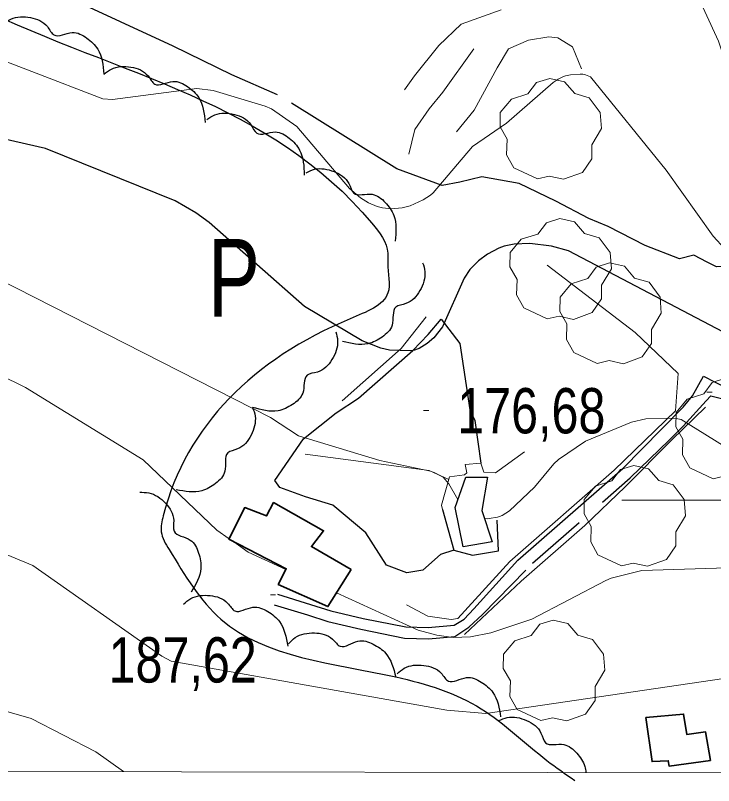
# Model space of a CAD drawing. Extents: x 483840 to 488445, y 4386047 to 4389027.
# Drawn here: x 484357.8 to 484492.8, y 4386444.9 to 4386593.6 of the extents above; entities that cross this region are included whole.
import ezdxf
from ezdxf.enums import TextEntityAlignment as Align

# ---------------------------------------------------------------- set-up
doc = ezdxf.new("R2010")
doc.units = 0
doc.header["$LTSCALE"] = 4
doc.linetypes.add('LONG_DASHED', pattern=[7.5, 6, -1.5])
doc.linetypes.add('MEDIUM_DASHED', pattern=[4.5, 3, -1.5])
for name, color, linetype, lineweight in [('1', 7, 'Continuous', 13), ('21', 7, 'Continuous', 25), ('25', 7, 'LONG_DASHED', 25), ('27', 7, 'Continuous', 25), ('29', 7, 'Continuous', 13), ('38', 7, 'Continuous', 25), ('46', 7, 'Continuous', 25), ('47', 7, 'Continuous', 35), ('51', 7, 'Continuous', 13), ('7', 7, 'Continuous', 13), ('8', 7, 'Continuous', 25), ('9', 7, 'Continuous', 13)]:
    doc.layers.add(name, color=color, linetype=linetype, lineweight=lineweight)
doc.layers.add('31', color=7, linetype='Continuous')

msp = doc.modelspace()

# ---------------------------------------------------------------- linework, layer by layer
at = {"layer": '1'}
msp.add_line((484475, 4386500), (484525, 4386500), dxfattribs=at)
msp.add_lwpolyline([(484110.5, 4388760.3), (487685.8, 4388753.5), (487681.9, 4386441.2), (484105.5, 4386448.1)], close=True, dxfattribs=at)
at = {"layer": '21'}
msp.add_lwpolyline([(484447.98, 4386497.99), (484449.95, 4386491.93), (484444.37, 4386490.96), (484442.82, 4386498.55), (484444.88, 4386504.43), (484449.1, 4386504.47)], close=True, dxfattribs=at)
at = {"layer": '25'}
for points in [[(484502.07, 4386561.29), (484498.4, 4386548.69), (484496.9, 4386545.14), (484493.33, 4386545.09), (484491.54, 4386545.96), (484488.97, 4386547.31), (484486.16, 4386546.59), (484479.53, 4386549.16), (484472.38, 4386552.84), (484468.67, 4386554.43), (484462.27, 4386557.73), (484455.18, 4386561.19), (484448, 4386562.42), (484443.71, 4386561.42), (484440.31, 4386560.77), (484431.57, 4386564.01), (484408.49, 4386578.31), (484399.65, 4386582.16), (484388.31, 4386587.7), (484360.41, 4386600.63)], [(484442.55, 4386490.37), (484439.96, 4386489.48), (484436.57, 4386486.47), (484433.51, 4386485.96), (484429.57, 4386487.41), (484425.55, 4386493.67), (484419.21, 4386499), (484413.91, 4386500.65), (484408.96, 4386502.45), (484407.95, 4386503.79), (484413.52, 4386511.87), (484419.84, 4386516.87), (484424.15, 4386519.68), (484434.64, 4386528.93), (484437.61, 4386532.01), (484440.13, 4386534.95), (484443.7, 4386530.23), (484445.64, 4386517.42), (484446.65, 4386515.37), (484447.8, 4386507.12)]]:
    msp.add_lwpolyline(points, dxfattribs=at)
at = {"layer": '27'}
for points in [[(484109.46, 4386593.06), (484150.94, 4386626.49), (484199.73, 4386650.7), (484203.95, 4386655.31), (484208.18, 4386661.85), (484210.1, 4386669.53), (484207.03, 4386691.82), (484208.56, 4386694.9), (484211.64, 4386696.82), (484215.48, 4386696.43), (484273.86, 4386668), (484283.08, 4386663), (484285.77, 4386658), (484291.92, 4386647.24), (484300.75, 4386636.1), (484310.35, 4386633.02), (484326.87, 4386627.64), (484334.94, 4386616.12), (484338.78, 4386603.82), (484350.3, 4386595.36), (484426.74, 4386553.47), (484429.82, 4386547.71), (484429.82, 4386545.79), (484429.82, 4386540.02), (484422.52, 4386535.03), (484386.41, 4386496.98), (484386.03, 4386493.91), (484387.56, 4386490.45), (484397.55, 4386477), (484431.35, 4386465.85), (484447.87, 4386459.7), (484460.55, 4386449.71), (484465.92, 4386445.87)], [(484355.5, 4386591.93), (484356.98, 4386592.9), (484360.76, 4386593.19), (484364.02, 4386591.46), (484365.3, 4386589.85), (484368.83, 4386590.31), (484371.62, 4386589.26), (484373.75, 4386587.11), (484374.94, 4386582.3)], [(484374.93, 4386582.28), (484376.4, 4386583.27), (484380.18, 4386583.63), (484383.47, 4386581.95), (484384.77, 4386580.36), (484388.29, 4386580.87), (484391.1, 4386579.87), (484393.27, 4386577.76), (484394.53, 4386572.96)], [(484394.84, 4386573.55), (484396.38, 4386574.43), (484400.18, 4386574.49), (484403.32, 4386572.56), (484404.5, 4386570.88), (484408.05, 4386571.11), (484410.77, 4386569.9), (484412.77, 4386567.62), (484413.66, 4386562.74)], [(484414.01, 4386563.24), (484415.65, 4386563.9), (484419.42, 4386563.46), (484422.28, 4386561.13), (484423.23, 4386559.3), (484426.77, 4386559.07), (484429.31, 4386557.5), (484430.98, 4386554.98), (484431.22, 4386550.02)], [(484436.54, 4386545.86), (484436.97, 4386544.13), (484436, 4386540.47), (484433.29, 4386537.96), (484431.36, 4386537.28), (484430.62, 4386533.8), (484428.71, 4386531.51), (484425.98, 4386530.2), (484421.05, 4386530.67)], [(484419.74, 4386532.51), (484420.11, 4386530.77), (484419, 4386527.14), (484416.2, 4386524.74), (484414.23, 4386524.13), (484413.37, 4386520.68), (484411.37, 4386518.46), (484408.6, 4386517.26), (484403.68, 4386517.92)], [(484403.66, 4386517.94), (484404.17, 4386516.24), (484403.38, 4386512.53), (484400.79, 4386509.89), (484398.89, 4386509.12), (484398.33, 4386505.61), (484396.53, 4386503.22), (484393.87, 4386501.79), (484388.92, 4386502.01)], [(484381.86, 4386501.51), (484383.63, 4386501.41), (484386.85, 4386499.41), (484388.44, 4386496.07), (484388.52, 4386494.02), (484391.63, 4386492.29), (484393.25, 4386489.79), (484393.69, 4386486.8), (484391.79, 4386482.22)], [(484390.32, 4386479.89), (484391.72, 4386480.98), (484395.47, 4386481.57), (484398.86, 4386480.1), (484400.26, 4386478.6), (484403.74, 4386479.33), (484406.61, 4386478.5), (484408.9, 4386476.53), (484410.47, 4386471.82)], [(484410.62, 4386472.27), (484411.93, 4386473.46), (484415.62, 4386474.35), (484419.11, 4386473.16), (484420.63, 4386471.77), (484424.04, 4386472.78), (484426.97, 4386472.19), (484429.41, 4386470.41), (484431.35, 4386465.84)], [(484431.59, 4386466.48), (484433, 4386467.55), (484436.76, 4386468.09), (484440.12, 4386466.57), (484441.51, 4386465.05), (484445, 4386465.73), (484447.85, 4386464.86), (484450.12, 4386462.86), (484451.61, 4386458.13)], [(484451.21, 4386457.41), (484452.88, 4386458.02), (484456.63, 4386457.44), (484459.41, 4386455.01), (484460.29, 4386453.15), (484463.82, 4386452.79), (484466.31, 4386451.13), (484467.89, 4386448.56), (484468.1, 4386447.4)]]:
    msp.add_spline(points, degree=3, dxfattribs=at)
at = {"layer": '29'}
for points in [[(484458.72, 4386562.05), (484454.18, 4386564.17), (484452.77, 4386566.71), (484452.87, 4386569.69), (484451.5, 4386572.1), (484451.54, 4386574.85), (484453.7, 4386577.45), (484456.89, 4386578.45), (484458.54, 4386580.64), (484461.11, 4386581.47), (484463.97, 4386580.82), (484465.92, 4386578.55), (484468.73, 4386577.73), (484470.86, 4386574.88), (484471.1, 4386571.75), (484469.22, 4386568.6), (484469.22, 4386565.92), (484467.4, 4386563.31), (484463.78, 4386561.97), (484461.01, 4386562.6)], [(484460.63, 4386535), (484456.09, 4386537.12), (484454.68, 4386539.66), (484454.78, 4386542.64), (484453.41, 4386545.05), (484453.45, 4386547.8), (484455.61, 4386550.4), (484458.8, 4386551.4), (484460.45, 4386553.59), (484463.02, 4386554.42), (484465.88, 4386553.77), (484467.83, 4386551.5), (484470.64, 4386550.68), (484472.77, 4386547.83), (484473.01, 4386544.7), (484471.13, 4386541.55), (484471.13, 4386538.87), (484469.31, 4386536.26), (484465.69, 4386534.92), (484462.92, 4386535.55)], [(484470.28, 4386526.4), (484465.74, 4386528.52), (484464.33, 4386531.06), (484464.43, 4386534.04), (484463.06, 4386536.45), (484463.1, 4386539.2), (484465.26, 4386541.8), (484468.45, 4386542.8), (484470.1, 4386544.99), (484472.67, 4386545.82), (484475.53, 4386545.17), (484477.48, 4386542.9), (484480.29, 4386542.08), (484482.42, 4386539.23), (484482.66, 4386536.1), (484480.78, 4386532.95), (484480.78, 4386530.27), (484478.96, 4386527.66), (484475.34, 4386526.32), (484472.57, 4386526.95)], [(484492.69, 4386504.12), (484488.15, 4386506.24), (484486.74, 4386508.78), (484486.84, 4386511.76), (484485.47, 4386514.17), (484485.51, 4386516.92), (484487.67, 4386519.52), (484490.86, 4386520.52), (484492.51, 4386522.71), (484495.08, 4386523.54), (484497.94, 4386522.89), (484499.89, 4386520.62), (484502.7, 4386519.8), (484504.83, 4386516.95), (484505.07, 4386513.82), (484503.19, 4386510.67), (484503.19, 4386507.99), (484501.37, 4386505.38), (484497.75, 4386504.04), (484494.98, 4386504.67)], [(484474.96, 4386487.3), (484470.42, 4386489.42), (484469.01, 4386491.96), (484469.11, 4386494.94), (484467.74, 4386497.35), (484467.78, 4386500.1), (484469.94, 4386502.7), (484473.13, 4386503.7), (484474.78, 4386505.89), (484477.35, 4386506.72), (484480.21, 4386506.07), (484482.16, 4386503.8), (484484.97, 4386502.98), (484487.1, 4386500.13), (484487.34, 4386497), (484485.46, 4386493.85), (484485.46, 4386491.17), (484483.64, 4386488.56), (484480.02, 4386487.22), (484477.25, 4386487.85)], [(484459.35, 4386457.43), (484454.81, 4386459.55), (484453.4, 4386462.09), (484453.5, 4386465.07), (484452.13, 4386467.48), (484452.17, 4386470.23), (484454.33, 4386472.83), (484457.52, 4386473.83), (484459.17, 4386476.02), (484461.74, 4386476.85), (484464.6, 4386476.2), (484466.55, 4386473.93), (484469.36, 4386473.11), (484471.49, 4386470.26), (484471.73, 4386467.13), (484469.85, 4386463.98), (484469.85, 4386461.3), (484468.03, 4386458.69), (484464.41, 4386457.35), (484461.64, 4386457.98)]]:
    msp.add_lwpolyline(points, close=True, dxfattribs=at)
at = {"layer": '38'}
msp.add_lwpolyline([(484408.47, 4386481.84), (484414.9, 4386479.86), (484418.79, 4386478.61), (484425.03, 4386477.17), (484433.29, 4386475.5), (484437.59, 4386475.39), (484442.65, 4386475.83), (484444.55, 4386477.03), (484446.43, 4386479.02), (484454.94, 4386488.38), (484475.25, 4386506.09), (484482.67, 4386513.7), (484486.88, 4386517.98), (484488.67, 4386520.12), (484490.84, 4386523.92), (484495.32, 4386521.66), (484501.58, 4386517.3), (484518.24, 4386506.36), (484559.23, 4386486.51), (484578.32, 4386474.6), (484591, 4386469.99)], dxfattribs=at)
at = {"layer": '38', "linetype": 'MEDIUM_DASHED'}
msp.add_lwpolyline([(484407.84, 4386479.79), (484414.26, 4386477.82), (484418.22, 4386476.54), (484424.58, 4386475.08), (484433.04, 4386473.36), (484437.66, 4386473.24), (484442.78, 4386473.67), (484445.47, 4386475.45), (484448.09, 4386477.89), (484457.74, 4386487.81), (484476.66, 4386504.31), (484484.2, 4386511.56), (484486.88, 4386514.29), (484491.35, 4386519.17), (484492.25, 4386520.12), (484494.29, 4386519.64), (484500.59, 4386515.38), (484517.18, 4386504.49), (484558.2, 4386484.63), (484577.38, 4386472.67), (484589.54, 4386468.24)], dxfattribs=at)
at = {"layer": '46'}
msp.add_lwpolyline([(484440.37, 4386498.21), (484442.55, 4386490.37), (484446.18, 4386489.37), (484451.19, 4386490.24), (484450.93, 4386496.12)], dxfattribs=at)
at = {"layer": '47'}
for points in [[(484422.7, 4386486.6), (484418.24, 4386479.44), (484408.63, 4386483.71), (484410.17, 4386486.76), (484399.12, 4386492.45), (484402.17, 4386498.55), (484406.38, 4386496.95), (484407.73, 4386499.54), (484417.41, 4386494.09), (484415.05, 4386491.03)], [(484479.69, 4386457.99), (484480.87, 4386449.52), (484484, 4386449.66), (484484.16, 4386448.62), (484492.15, 4386449.72), (484491.21, 4386455.23), (484487.56, 4386454.74), (484486.95, 4386458.69)]]:
    msp.add_lwpolyline(points, close=True, dxfattribs=at)
at = {"layer": '51'}
for points in [[(484451.74, 4386594.71), (484444.01, 4386591.92), (484439.66, 4386587.8), (484434.99, 4386581.93), (484433.06, 4386579.22)], [(484467.24, 4386583.32), (484465.52, 4386587.57), (484462.67, 4386589.28), (484460.94, 4386589.48), (484456.97, 4386588.83), (484453.13, 4386587.14), (484450.91, 4386583.51), (484446.5, 4386575.33), (484443.09, 4386571.13)], [(484446.44, 4386587.17), (484440.44, 4386578.8), (484437.79, 4386575.59), (484435.04, 4386571.58), (484433.9, 4386566.8)], [(484460.62, 4386545.39), (484477.61, 4386532.37), (484485.94, 4386524.43), (484485.42, 4386517.27)], [(484421, 4386519.19), (484432.41, 4386529.26), (484437.22, 4386535.4)], [(484491.22, 4386517.99), (484484.72, 4386511.63), (484475.66, 4386502.59), (484467.87, 4386495.11), (484455.61, 4386484.34), (484444.65, 4386474.08)], [(484433.45, 4386479.79), (484437.56, 4386477.58), (484442.04, 4386476.95), (484443.35, 4386477.14), (484453.36, 4386488.14), (484473.55, 4386505.77), (484485.42, 4386517.27)], [(484456.2, 4386509.31), (484450.65, 4386505.25), (484448.34, 4386505.43), (484447.8, 4386507.12), (484444.77, 4386506.86), (484445.07, 4386505.28), (484444.65, 4386504.9), (484441.76, 4386504.52), (484440.17, 4386499.05), (484440.37, 4386498.21)], [(484441.62, 4386504), (484437.78, 4386505.71), (484413.87, 4386508.91)]]:
    msp.add_lwpolyline(points, dxfattribs=at)
at = {"layer": '7'}
for p, q in [((484491.47, 4386520.84), (484492.47, 4386520.84)), ((484436.71, 4386517.3), (484437.71, 4386517.3)), ((484407.11, 4386481.71), (484408.11, 4386481.71))]:
    msp.add_line(p, q, dxfattribs=at)
at = {"layer": '8'}
msp.add_lwpolyline([(484515.43, 4386521.59), (484464.75, 4386548.15), (484461.45, 4386549.08), (484457.25, 4386549.56), (484454.21, 4386549.42), (484452.3, 4386549.05), (484451.27, 4386548.67), (484449.08, 4386547.52), (484447.32, 4386546.22), (484445.69, 4386544.56), (484444.57, 4386542.87), (484440.37, 4386533.47), (484438.68, 4386531.36), (484437.39, 4386530.25), (484435.85, 4386529.32), (484435.5, 4386529.17), (484434.94, 4386529), (484434.24, 4386528.87), (484430.11, 4386528.96), (484428.43, 4386529.36), (484424.85, 4386530.79), (484413.69, 4386537.38), (484395.27, 4386553.63), (484392.74, 4386555.52), (484388.7, 4386557.8), (484363.67, 4386567.9), (484346.43, 4386571.82)], dxfattribs=at)
at = {"layer": '9'}
msp.add_line((484399.74, 4386492.13), (484399.77, 4386492.11), dxfattribs=at)
for points in [[(484488.8, 4386599.35), (484493.7, 4386588.66), (484495.64, 4386582.81), (484496.25, 4386581.43), (484500.96, 4386575.68), (484519.23, 4386560.78), (484521.43, 4386559.3), (484539.15, 4386551.29), (484541.58, 4386550.7), (484559.86, 4386549.15), (484568.49, 4386549.51), (484572.38, 4386550.33), (484574.17, 4386550.91), (484575.85, 4386551.84), (484577.16, 4386553.09), (484578.25, 4386554.59), (484586.98, 4386573.64), (484587.78, 4386577.36), (484587.73, 4386610.21)], [(484494.95, 4386548.53), (484492.65, 4386551.01), (484483.61, 4386563.72), (484468.97, 4386581.76), (484468.04, 4386582.14), (484467.51, 4386582.26), (484466.95, 4386582.3), (484465.08, 4386582.16), (484464.16, 4386581.96), (484463.65, 4386581.76), (484462.75, 4386581.32), (484461.79, 4386580.66), (484452.73, 4386572.81), (484446.15, 4386568.28), (484438.59, 4386559.38), (484438.07, 4386558.93), (484436.66, 4386557.98), (484434.11, 4386556.83), (484432.6, 4386556.46), (484430.46, 4386556.28), (484428.79, 4386556.45), (484427.72, 4386556.72), (484426.08, 4386557.4), (484424.53, 4386558.36), (484422.38, 4386560.17), (484412.2, 4386572.18), (484407.36, 4386575.56), (484406.13, 4386576.09), (484396.08, 4386579.15), (484392.91, 4386579.52), (484376.58, 4386577.36), (484374.77, 4386577.51), (484347.24, 4386588.08)], [(484143.24, 4386448.03), (484144.73, 4386448.77), (484161.44, 4386465.03), (484176.34, 4386483.25), (484221.45, 4386517.27), (484235.16, 4386524.61), (484305.66, 4386553), (484309.72, 4386553.93), (484321.3, 4386553.85), (484335.62, 4386551.25), (484340.44, 4386549.87), (484407.12, 4386515.96), (484412.52, 4386512.39), (484428.24, 4386507.63), (484438.05, 4386505.61), (484438.79, 4386505.37), (484440.5, 4386504.45), (484441.58, 4386503.17), (484443.37, 4386500.11)], [(484157.47, 4386448), (484159.38, 4386449.87), (484189.58, 4386483.98), (484198.35, 4386491.47), (484211.81, 4386500.24), (484289.55, 4386533.44), (484303.86, 4386537.4), (484308.13, 4386538.16), (484314.22, 4386538.31), (484322.79, 4386537.25), (484334.66, 4386534.14), (484359.78, 4386521.76), (484382.51, 4386507.78), (484396.76, 4386494.23), (484399.16, 4386492.54)], [(484448.48, 4386496.46), (484448.98, 4386496.42), (484449.4, 4386496.43), (484451, 4386496.72), (484451.37, 4386496.83), (484451.9, 4386497.05), (484453.35, 4386497.91), (484458.13, 4386502.49), (484461.87, 4386506.99), (484462.78, 4386507.86), (484467.98, 4386511.37), (484476.93, 4386515.03), (484479.7, 4386515.68), (484484.76, 4386515.86), (484485.5, 4386515.79), (484486.52, 4386515.57), (484498, 4386508.44)], [(484585.35, 4386447.17), (484571.82, 4386453.51), (484543.8, 4386461.31), (484501.29, 4386466.52), (484448.74, 4386458.82), (484441.24, 4386459.42), (484387.93, 4386468.88), (484386.11, 4386469.88), (484361.22, 4386487.35), (484320.5, 4386504.22), (484291.24, 4386508.06), (484269.99, 4386506.78), (484266.07, 4386505.63), (484212.71, 4386477.42), (484197.86, 4386466.42), (484179.22, 4386447.96)], [(484399.77, 4386492.11), (484402.81, 4386489.98), (484410.1, 4386486.63)], [(484419.91, 4386482.12), (484435.65, 4386474.88), (484439.31, 4386473.89), (484442.47, 4386473.44), (484445.81, 4386473.58), (484449.7, 4386474.35), (484457.67, 4386477.03), (484471.94, 4386484.5), (484473, 4386484.93), (484478.92, 4386486.4), (484499.51, 4386487.08), (484517.85, 4386485.38), (484606.36, 4386460.28), (484628.46, 4386450.94), (484631.38, 4386448.98), (484633.01, 4386447.08)], [(484378.75, 4386447.57), (484373.39, 4386451.42), (484360.91, 4386457.85), (484294.23, 4386477.01), (484290.34, 4386477.36), (484260.85, 4386476.52), (484243.58, 4386473.23), (484224.58, 4386465.82), (484198.25, 4386447.92)]]:
    msp.add_lwpolyline(points, dxfattribs=at)

# ---------------------------------------------------------------- texts
at = {"layer": '31', "width": 0.75}
msp.add_text('P', height=15, dxfattribs=at).set_placement((484400.08, 4386535.44), align=Align.CENTER)
at = {"layer": '7', "width": 0.8}
for s, p in [('176,68', (484443.22, 4386512.89)), ('187,62', (484375.85, 4386464.77))]:
    msp.add_text(s, height=8.75, dxfattribs=at).set_placement(p)

doc.saveas('drawing.dxf')
